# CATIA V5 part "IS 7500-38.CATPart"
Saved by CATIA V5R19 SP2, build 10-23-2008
Part number: IS 7500-38
Bounding box of the stored display mesh (mm): x -74.81 to 74.81, y -74.81 to 74.81, z 0 to 231
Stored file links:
  C:\Users\Bora\Desktop\3D Katı model\IS serisi\IS 7500\IS 7500-38.CATPart
  C:\Program Files\Dassault Systemes\B19\intel_a\reffiles\standard\MetricThickPitch.txt
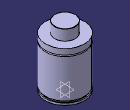
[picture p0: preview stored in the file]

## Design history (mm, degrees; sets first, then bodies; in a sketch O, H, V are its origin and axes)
Body1 (main body)
  Sketch1 on yz-plane, origin (0, 0, 0), H (0, 1, 0), V (0, 0, 1)
    point P1 (75, 168)
    point P4 (75, 163)
    point P7 (40, 230)
    point P9 (40, 230)
    point P13 (75, 168)
    point P14 (75, 163)
    line L1 (75, 168) -> (75, 190)
    line L2 (75, 15) -> (75, 163)
    line L3 (71, 15) -> (71, 8)
    arc A1 centre (39, 230) radius 1 from (40, 230) to (39, 231) ccw
    line L4 (40, 230) -> (40, 190)
    line L5 (75, 0) -> (75, 8)
    arc A2 centre (75, 165.5) radius 2.5 from (75, 168) to (75, 163) ccw
    line L6 (39, 231) -> (0, 231)
    point P15 (0, 231)
    line L7 (40, 190) -> (75, 190)
    line L8 (0, 0) -> (75, 0)
    line L9 (71, 15) -> (75, 15)
    line L10 (71, 8) -> (75, 8)
    coincidence: P15 V, P1 P13, P4 P14, P7 P9
    tangency: L6 A1
    horizontal: L7 H, L8 H, L9 H, L10 H
  Shaft1: profile Sketch1, axis Sketch1.V, angle 360
  Sketch2 on face of Shaft1 from Sketch1.L8, origin (0, 0, 0), H (1, 0, 0), V (0, -1, 0)
    point P1 (50, 0)
    distance P1 V = 50
  Hole1: placed by Sketch2, at (50, 0, 0) direction (0, 0, 1), diameter 8.376, depth 16, threaded "M10", thread diameter 10, thread depth 16, pitch 1.5
  CircPattern1: of Hole1, instances 4, angular step 90, axis from xy-plane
